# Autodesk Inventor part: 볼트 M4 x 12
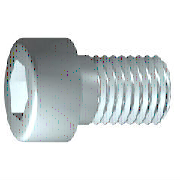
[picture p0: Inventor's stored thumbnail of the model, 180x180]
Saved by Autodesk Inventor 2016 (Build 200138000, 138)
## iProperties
IsCustomPart: 1
Created: 2012-02
Part Number: 볼트 M4 x 12
Material: 스테인리스강
Description: 6각 소켓 머리 캡 나사
Document SubType Name: Modeling
Standard: ISO 4762
Designer: mduedu
Standard Revision: Fourth edition 2004-03-01
Standards Organization: ISO
Language: ko-KR
Size Designation: M4 x 12
Categories: <MemberInstance><Categories><Category DisplayName="조임쇠" InternalName="e4da775c-781d-43d5-af7c-5136215cf5a6" Mnemonic="FSTN"><Category DisplayName="볼트" InternalN
Density: 8.08 g/cm^3
Appearance: 반광택
Mass: 2.2972 g
Surface Area: 3.30853 cm^2
Volume: 0.284306 cm^3
Author: mduedu
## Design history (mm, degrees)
sketch "스케치1"
  geometry: L1 (-1, 0)-(12, 0); L2 (12, 0)-(12, 2); L3 (12, 2)-(1.75, 2); L4 (1.75, 2)-(1.32, 2); L5 (1.32, 2)-(0, 2); L6 (0, 2)-(0, 3.5); L7 (0, 3.5)-(-4, 3.5); L8 (-4, 3.5)-(-4, 1.732); L9 (-4, 1.732)-(-2, 1.732); L10 (-2, 1.732)-(-1, 0); L11 (-7.2, 0)-(15.2, 0) reference; L12 (0, -0.7)-(0, 4.2) reference; L13 (1.75, 2)-(0, 2)
  constraints: 22 end point, 6 parallel, 2 collinear, 2 perpendicular, 1 horizontal, 1 point on line
  dimensions: "d1" = 10.25 distance from line of L3.end L2 (= GEL); "d2" = 0.42952 distance of L4.end L3.end (computed from GAL); "d3" = 4 distance between parallel lines of L8 L6 (= KOH); "d4" = 2 distance of L8.end L9.end (= INTI); "d5" = 60 deg angle of L10 L1; "d6" = 4 diameter of L3 L1 (= GD); "d7" = 4 diameter of L5 L1 (= BDM); "d8" = 3.4641 diameter of L9 L1 (= 1.1547 x SW); "d9" = 7 diameter of L7 L1 (= KOD); "d26" = 12 distance between parallel lines of L12 L2 (= NLG)
revolve "본체" sketch "스케치1" stored, may be unused: angle "d10" = 90 deg
sketch "스케치2"
  geometry: L1 (0, -4.9)-(0, 4.9) reference; L2 (-4.9, 0)-(4.9, 0) reference; L3 (1.732, 0)-(0.866, -1.5); L4 (0.866, -1.5)-(-0.866, -1.5); L5 (-0.866, -1.5)-(-1.732, 0); L6 (-1.732, 0)-(-0.866, 1.5); L7 (-0.866, 1.5)-(0.866, 1.5); L8 (0.866, 1.5)-(1.732, 0); 2 further points
  constraints: 12 end point, 1 coincident, 1 horizontal alignment, 1 point on line, 12 other
extrude "슬롯" join sketch "스케치2" stored distance "d11" = 10; taper "d12" = 0 deg
workplane "Work Plane1"
fillet "Fillet2" dims "d30" = 0.1 (= R)
body "Solid1"
fillet "모깎기1" dims "d17" = 0.4 (= RR)
feature "스레드" dims "d13" = 10.25 (= GEL), "d14" = 0
chamfer "모따기1" distance "d15" = 0.42941 (= -0.5 x SPD + 0.5 x GD); stored, may be unused: second distance "d16" = 0.42941 (= GUL), angle "d27" = 45 deg
other parameters: "GD" = 4 [user parameter; used in 2 equation terms], "NLG" = 12 [user parameter; used in 1 equation term], "GEL" = 10.25 [user parameter; used in 2 equation terms], "KOD" = 7 [user parameter; used in 1 equation term], "KOH" = 4 [user parameter; used in 1 equation term], "INTI" = 2 [user parameter; used in 1 equation term], "GAL" = 0.42941 (= 0.61345 x PTC) [user parameter; used in 1 equation term], "GUL" = 0.42941 (= 0.61345 x PTC) [user parameter; used in 1 equation term], "BDM" = 4 (= NND) [user parameter; used in 1 equation term], "SW" = 3 [user parameter; used in 2 equation terms], "RR" = 0.4 [user parameter; used in 1 equation term], "SPD" = 3.14117 (= NND - 1.2269 x PTC) [user parameter; used in 1 equation term], "d19" = 0, "d28" = 0, "d29" = 0, "R" = 0.1 [user parameter; used in 1 equation term], "TOA" = 30 deg [user parameter], "GD1" = 3.14117 (= THREADDIA - 1.2269 x PTC) [user parameter], "THREADDIA" = 4 [user parameter; used in 1 equation term], "FAWI" = 45 deg [user parameter], "TPU" = 14.28571 (computed from PTC) [user parameter], "PTC" = 0.7 [user parameter; used in 5 equation terms], "NND" = 4 [user parameter; used in 2 equation terms], "E0" = 3.465 (= 1.155 x SW) [user parameter]
